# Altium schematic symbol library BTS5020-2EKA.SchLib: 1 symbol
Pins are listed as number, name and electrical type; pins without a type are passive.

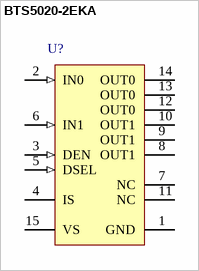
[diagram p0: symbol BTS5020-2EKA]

## BTS5020-2EKA
designator U?
PROFET+ 12 V Smart High-Side Power Switch, 1 Channel, 20 mOhm, 50 A Load Current, -40 to 150 degC, PG-DSO-14-47, Tube, Green; Manufacturer: Infineon; PartNumber: BTS5020-2EKA; Channels: 2; Green: TRUE; Group: Automotive Qualified; Load Current (typ): 50 A; Ptot (max): 2.2 W; Recommended Operating Voltage Max.: 28 V; Recommended Operating Voltage Min.: 5 V; RON @ 25degreesC: 20 mOhm; RON(max) @ 150degreesC: 44 mOhm; toff (max): 230 us
footprint INF-PG-DSO-14-47_N (SOP, 14-Leads, Body 8.65x3.9mm, Pitch 1.27mm, Thermal Pad 6500x2750mm, IPC Medium Density)
footprint INF-PG-DSO-14-47_L (SOP, 14-Leads, Body 8.65x3.9mm, Pitch 1.27mm, Thermal Pad 6500x2750mm, IPC High Density)
footprint INF-PG-DSO-14-47_M (SOP, 14-Leads, Body 8.65x3.9mm, Pitch 1.27mm, Thermal Pad 6500x2750mm, IPC Low Density)
pins: 1 GND (power) "GrouND; Ground connection", 2 IN0 (in) "INput channel 0; Input signal for channel 0 activation", 3 DEN (in) "Diagnostic ENable; Digital signal to enable/disable the diagnosis of the device", 4 IS (hiz) "Sense; Sense current of the selected channel", 5 DSEL (in) "Diagnostic SELection; Digital signal to select the channel to be diagnosed", 6 IN1 (in) "INput channel 1; Input signal for channel 1 activation", 7 NC "Not Connected; No internal connection to the chip", 8 OUT1 (power) "OUTput 1; Protected high side power output channel 1", 9 OUT1 (power) "OUTput 1; Protected high side power output channel 1", 10 OUT1 (power) "OUTput 1; Protected high side power output channel 1", 11 NC "Not Connected; No internal connection to the chip", 12 OUT0 (power) "OUTput 0; Protected high side power output channel 0", 13 OUT0 (power) "OUTput 0; Protected high side power output channel 0", 14 OUT0 (power) "OUTput 0; Protected high side power output channel 0", 15 VS (power) "Voltage Supply; Battery voltage"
